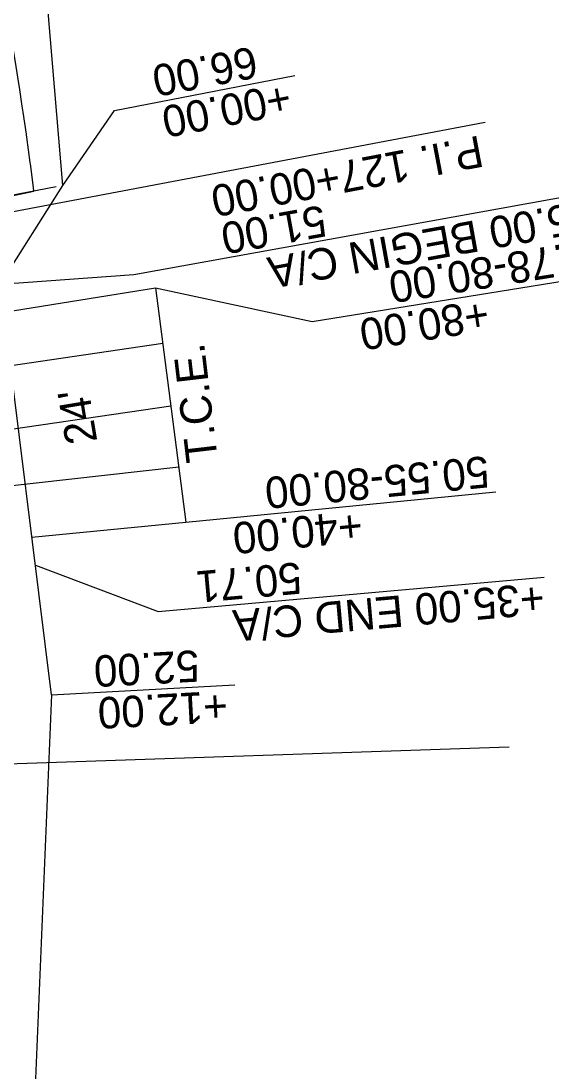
# Model space of a CAD drawing. Extents: x -70 to 701944, y -4 to 666871.
# Drawn here: x 668373.6 to 668474.7, y 655786.4 to 655986.6 of the extents above; entities that cross this region are included whole.
import ezdxf

# ---------------------------------------------------------------- set-up
doc = ezdxf.new("R2010")
doc.units = 0
for name, color, linetype in [('R_Detour', 7, 'Continuous'), ('R_Drive', 7, 'Continuous'), ('R_Horz Alg Annot', 7, 'Continuous'), ('R_No Plot', 7, 'Continuous'), ('R_Proposed Const Limits', 7, 'Continuous'), ('R_ROW', 7, 'Continuous'), ('R_ROW Annot', 7, 'Continuous'), ('R_Temp Easement', 7, 'Continuous'), ('R_Temp Easement Annot', 7, 'Continuous')]:
    doc.layers.add(name, color=color, linetype=linetype)

msp = doc.modelspace()

# ---------------------------------------------------------------- linework, layer by layer
at = {"layer": 'R_Detour'}
for p, q in [((668380.25, 655954.93), (668315.18, 655942.32)), ((668466.54, 655848.1), (668327.94, 655843.36))]:
    msp.add_line(p, q, dxfattribs=at)
at = {"layer": 'R_Drive'}
for p, q in [((668363.69, 655919.71), (668400.54, 655925.1)), ((668366.57, 655897.38), (668403.59, 655901.53))]:
    msp.add_line(p, q, dxfattribs=at)
at = {"layer": 'R_Horz Alg Annot'}
msp.add_lwpolyline([(668334.77, 655943.2), (668461.97, 655967.26)], dxfattribs=at)
at = {"layer": 'R_No Plot'}
msp.add_line((668365.43, 655907.84), (668402.08, 655913.19), dxfattribs=at)
at = {"layer": 'R_Proposed Const Limits'}
msp.add_lwpolyline([(668359.13, 655950.56), (668376, 655954.1), (668375.91, 655954.81), (668375.35, 655959.33), (668375.31, 655959.6), (668374.66, 655964.38), (668374.6, 655964.82), (668374.57, 655964.99), (668373.97, 655969.16), (668373.8, 655970.32), (668373.26, 655973.94), (668372.96, 655975.81), (668372.95, 655975.86), (668372.48, 655978.7), (668372.04, 655981.28), (668371.67, 655983.46), (668371.2, 655986.73)], dxfattribs=at)
at = {"layer": 'R_ROW'}
for points in [[(668381.5, 655955.17), (668373.32, 656052.3), (668331.42, 656174.44), (668303.61, 656343.73), (668341.52, 656413.55)], [(668379.35, 655858.1), (668369.67, 655936.38), (668381.5, 655955.17)], [(668379.35, 655858.1), (668375.98, 655777.07), (668370.36, 655679.23), (668386.89, 655520.28), (668407.12, 655376.16), (668401.28, 655337.39), (668367.53, 655300.94), (668336.13, 654741.8), (668319.02, 654252.06), (668346.25, 654066.79), (668364.92, 653986.53), (668401.01, 653983.18), (668425.78, 653872.16), (668398.63, 653868.03), (668433.79, 653730.98), (668450.99, 653639.16), (668466.96, 653535.35), (668502.13, 653505.82)]]:
    msp.add_lwpolyline(points, dxfattribs=at)
at = {"layer": 'R_ROW Annot'}
for points in [[(668381.5, 655955.17), (668391.33, 655969.48), (668425.69, 655976.14)], [(668369.67, 655936.38), (668395.05, 655938.23), (668483.97, 655954.3)], [(668376.29, 655882.8), (668399.7, 655873.94), (668473.17, 655880.51)], [(668379.35, 655858.1), (668414.3, 655859.96)]]:
    msp.add_lwpolyline(points, dxfattribs=at)
at = {"layer": 'R_Temp Easement'}
for p, q in [((668370.33, 655931.01), (668399.18, 655935.66)), ((668399.18, 655935.66), (668404.94, 655891.02)), ((668375.63, 655888.16), (668404.94, 655891.02))]:
    msp.add_line(p, q, dxfattribs=at)
at = {"layer": 'R_Temp Easement Annot'}
for points in [[(668399.18, 655935.66), (668429.01, 655929.24), (668486.85, 655938.57)], [(668404.94, 655891.02), (668463.99, 655896.76)]]:
    msp.add_lwpolyline(points, dxfattribs=at)

# ---------------------------------------------------------------- texts
at = {"layer": 'R_Drive'}
msp.add_text("24'", height=6, rotation=99.3805, dxfattribs=at).set_placement((668388.1, 655906.41))
at = {"layer": 'R_Horz Alg Annot'}
msp.add_text('P.I. 127+00.00', height=6, rotation=190.7106, dxfattribs=at).set_placement((668460.89, 655964.76))
at = {"layer": 'R_ROW Annot'}
for s, rotation, p in [('66.00', 190.961, (668417.88, 655981.76)), ('+00.00', 190.961, (668424.32, 655974.85)), ('51.00', 190.241, (668431.06, 655951.49)), ('+85.00 BEGIN C/A', 190.241, (668486.67, 655953.4)), ('50.71', 185.111, (668426.71, 655883.38)), ('+35.00 END C/A', 185.111, (668472.97, 655879.49)), ('52.00', 183.041, (668407.34, 655866.6)), ('+12.00', 183.041, (668412.76, 655858.88))]:
    msp.add_text(s, height=6, rotation=rotation, dxfattribs=at).set_placement(p)
at = {"layer": 'R_Temp Easement Annot'}
for s, rotation, p in [('50.78-80.00', 189.161, (668485.56, 655945.45)), ('+80.00', 189.161, (668462.15, 655933.57)), ('T.C.E.', 96.6917, (668411.05, 655902.77)), ('50.55-80.00', 185.561, (668462.4, 655903.64)), ('+40.00', 185.561, (668438.29, 655893.26))]:
    msp.add_text(s, height=6, rotation=rotation, dxfattribs=at).set_placement(p)

doc.saveas('drawing.dxf')
